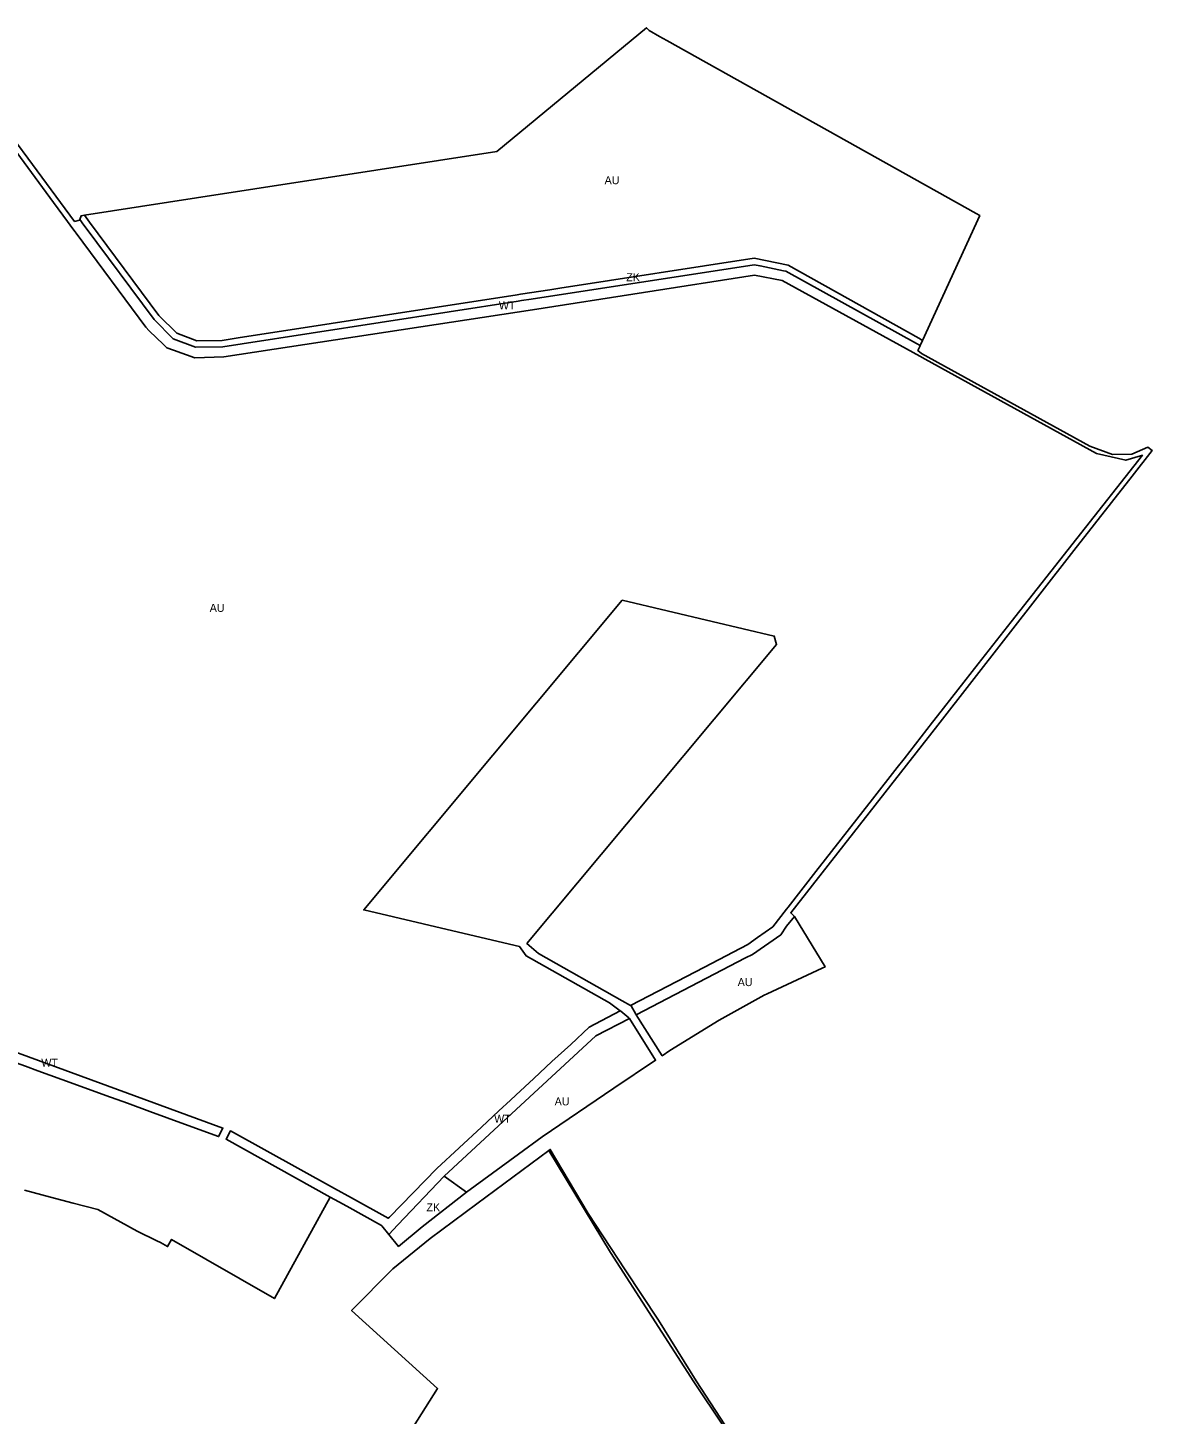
# Model space of a CAD drawing. Extents: x -541351 to -537540, y -1162694 to -1159725.
# Drawn here: x -538243 to -537540, y -1161316 to -1160450 of the extents above; entities that cross this region are included whole.
import ezdxf

# ---------------------------------------------------------------- set-up
doc = ezdxf.new("R2010")
doc.units = 0
for name, color, linetype in [('90640013', 7, 'Continuous'), ('90710013', 7, 'Continuous'), ('90750013', 7, 'Continuous')]:
    doc.layers.add(name, color=color, linetype=linetype)

msp = doc.modelspace()

# ---------------------------------------------------------------- linework, layer by layer
at = {"layer": '90640013'}
msp.add_lwpolyline([(-538279, -1160482.96), (-538213.92, -1160570.92), (-538210.85, -1160570.08), (-538210.69, -1160569.68), (-538208.11, -1160573.15), (-538207.25, -1160574.31), (-538164.14, -1160632.26), (-538152.14, -1160644.18), (-538138.21, -1160649.42), (-538121.28, -1160649.23), (-538109.03, -1160647.34), (-537936.47, -1160620.64), (-537934.5, -1160620.33), (-537928.39, -1160619.39), (-537789.11, -1160597.93), (-537785.28, -1160598.72), (-537770.7, -1160601.72), (-537769.21, -1160602.03), (-537687.55, -1160647.19), (-537685.23, -1160648.47), (-537685.51, -1160649.08), (-537686.66, -1160651.61), (-537684.47, -1160653.51), (-537579.13, -1160711.27), (-537565.07, -1160716.59), (-537552.97, -1160716.32), (-537542.86, -1160712.01), (-537540.13, -1160714.12), (-537552.67, -1160730.05), (-537589.07, -1160776.48), (-537674.22, -1160885.61), (-537766.11, -1161003.04), (-537763.7, -1161005.27), (-537768.77, -1161011.34), (-537772.4, -1161016.83), (-537790.07, -1161028.95), (-537794.44, -1161031.23), (-537862.75, -1161066.81), (-537863.04, -1161066.36), (-537865.95, -1161061.12), (-537866.26, -1161060.95), (-537820.17, -1161036.95), (-537802.13, -1161027.56), (-537793.05, -1161022.83), (-537786.92, -1161018.47), (-537777.42, -1161011.72), (-537768.74, -1161000.61), (-537767.82, -1160999.43), (-537750.43, -1160977.17), (-537715.05, -1160931.9), (-537699.56, -1160912.07), (-537695.33, -1160906.66), (-537677.47, -1160883.81), (-537674.39, -1160879.87), (-537648.96, -1160847.33), (-537628.36, -1160821.2), (-537546.25, -1160717.06), (-537547.58, -1160717.45), (-537556.76, -1160720.12), (-537575.01, -1160716.01), (-537682.14, -1160657.06), (-537685.53, -1160655.19), (-537771.5, -1160607.84), (-537788.88, -1160604.48), (-537927.57, -1160626.04), (-538120.6, -1160655.48), (-538138.75, -1160656.03), (-538151.96, -1160651.42), (-538156.16, -1160649.95), (-538158.3, -1160647.86), (-538167.16, -1160639.19), (-538169.34, -1160637.06), (-538212.88, -1160578.2), (-538213.5, -1160577.37), (-538214.91, -1160575.46), (-538218.22, -1160570.98), (-538227.05, -1160559.02), (-538238.54, -1160543.48), (-538272.58, -1160497.42)], dxfattribs=at)
for points in [[(-538375.11, -1161055.56), (-538368.36, -1161057.14), (-538292.2, -1161074.93), (-538121.13, -1161137.53), (-538123.8, -1161142.88), (-538145.25, -1161135.18), (-538166.87, -1161127.08), (-538180.71, -1161122.06), (-538194.34, -1161117.12), (-538209.76, -1161111.53), (-538221.89, -1161107.13), (-538236.85, -1161101.71), (-538244.47, -1161098.87), (-538261.65, -1161092.73), (-538269.37, -1161089.96), (-538288.24, -1161082.83), (-538291.28, -1161081.71), (-538292.78, -1161081.15), (-538313.99, -1161076.13), (-538334.92, -1161071.21), (-538344.15, -1161068.97), (-538360.05, -1161065.13), (-538370.98, -1161062.77)], [(-538017.371, -1161203.989), (-538021.73, -1161198.6), (-538021.99, -1161198.46), (-538043.663, -1161186.43), (-538048.69, -1161183.64), (-538054.155, -1161180.606), (-538054.155, -1161180.606), (-538119.15, -1161144.52), (-538116.49, -1161139.32), (-538051.28, -1161175.369), (-538040.778, -1161181.175), (-538017.76, -1161193.9), (-538017.1, -1161193.19), (-537987.47, -1161162.86), (-537959.49, -1161136.9), (-537948.57, -1161126.77), (-537941.41, -1161120.13), (-537938.08, -1161117.04), (-537926.78, -1161106.53), (-537915.45, -1161096.02), (-537903.69, -1161085.29), (-537892.24, -1161074.47), (-537872.72, -1161064.31), (-537872.42, -1161064.54), (-537867.27, -1161068.59), (-537867, -1161069.02), (-537887.98, -1161079.94), (-537948.84, -1161136.22), (-537982.73, -1161167.56), (-538011.8, -1161198.06)]]:
    msp.add_lwpolyline(points, close=True, dxfattribs=at)
at = {"layer": '90710013'}
for points in [[(-537770.7, -1160601.72), (-537785.28, -1160598.72), (-537789.11, -1160597.93), (-537928.39, -1160619.39), (-537934.5, -1160620.33), (-537936.47, -1160620.64), (-538109.03, -1160647.34), (-538121.28, -1160649.23), (-538138.21, -1160649.42), (-538152.14, -1160644.18), (-538164.14, -1160632.26), (-538207.25, -1160574.31), (-538208.11, -1160573.15), (-538210.69, -1160569.68), (-538209.76, -1160567.34), (-538207.69, -1160567.02), (-538204.55, -1160571.24), (-538161.11, -1160629.63), (-538149.93, -1160640.74), (-538137.51, -1160645.41), (-538121.61, -1160645.23), (-538111.7, -1160643.7), (-537937.08, -1160616.69), (-537935.11, -1160616.38), (-537916.68, -1160613.54), (-537910.61, -1160612.61), (-537789.01, -1160593.87), (-537767.82, -1160598.23), (-537686.06, -1160643.92), (-537683.74, -1160645.22), (-537685.23, -1160648.47), (-537687.55, -1160647.19), (-537769.21, -1160602.03)], [(-538017.371, -1161203.989), (-538011.8, -1161198.06), (-537982.73, -1161167.56), (-537968.86, -1161177.68), (-537996.47, -1161199.19), (-538011.287, -1161211.511)]]:
    msp.add_lwpolyline(points, close=True, dxfattribs=at)
msp.add_lwpolyline([(-537771.59, -1161378.63), (-537826.79, -1161296.05), (-537878.78, -1161215.29), (-537917.43, -1161151.64), (-537916.45, -1161150.91), (-537892.7, -1161190.89), (-537869.6, -1161226.04), (-537848.8, -1161257.55), (-537825.35, -1161295.54), (-537795.27, -1161341.6)], dxfattribs=at)
at = {"layer": '90750013'}
for points in [[(-537683.74, -1160645.22), (-537686.06, -1160643.92), (-537767.82, -1160598.23), (-537789.01, -1160593.87), (-537910.61, -1160612.61), (-537916.68, -1160613.54), (-537935.11, -1160616.38), (-537937.08, -1160616.69), (-538111.7, -1160643.7), (-538121.61, -1160645.23), (-538137.51, -1160645.41), (-538149.93, -1160640.74), (-538161.11, -1160629.63), (-538204.55, -1160571.24), (-538207.69, -1160567.02), (-538137.75, -1160556.21), (-537949.87, -1160527.25), (-537856.38, -1160449.82), (-537854.65, -1160451.57), (-537848.19, -1160455.22), (-537843.64, -1160457.79), (-537650.31, -1160565.94), (-537648.03, -1160567.22)], [(-537763.7, -1161005.27), (-537744.73, -1161036.78), (-537746.54, -1161037.51), (-537780.97, -1161053.72), (-537782.71, -1161054.54), (-537810.83, -1161070.12), (-537841.77, -1161089.11), (-537846.51, -1161092.3), (-537862.75, -1161066.81), (-537794.44, -1161031.23), (-537790.07, -1161028.95), (-537772.4, -1161016.83), (-537768.77, -1161011.34)], [(-537867, -1161069.02), (-537850.7, -1161095.11), (-537876.65, -1161112.57), (-537921.55, -1161143.01), (-537936.28, -1161153.8), (-537968.86, -1161177.68), (-537982.73, -1161167.56), (-537948.84, -1161136.22), (-537887.98, -1161079.94)]]:
    msp.add_lwpolyline(points, close=True, dxfattribs=at)
for points in [[(-538272.58, -1160497.42), (-538238.54, -1160543.48), (-538227.05, -1160559.02), (-538218.22, -1160570.98), (-538214.91, -1160575.46), (-538213.5, -1160577.37), (-538212.88, -1160578.2), (-538169.34, -1160637.06), (-538167.16, -1160639.19), (-538158.3, -1160647.86), (-538156.16, -1160649.95), (-538151.96, -1160651.42), (-538138.75, -1160656.03), (-538120.6, -1160655.48), (-537927.57, -1160626.04), (-537788.88, -1160604.48), (-537771.5, -1160607.84), (-537685.53, -1160655.19), (-537682.14, -1160657.06), (-537575.01, -1160716.01), (-537556.76, -1160720.12), (-537547.58, -1160717.45), (-537546.25, -1160717.06), (-537628.36, -1160821.2), (-537648.96, -1160847.33), (-537674.39, -1160879.87), (-537677.47, -1160883.81), (-537695.33, -1160906.66), (-537699.56, -1160912.07), (-537715.05, -1160931.9), (-537750.43, -1160977.17), (-537767.82, -1160999.43), (-537768.74, -1161000.61), (-537777.42, -1161011.72), (-537786.92, -1161018.47), (-537793.05, -1161022.83), (-537802.13, -1161027.56), (-537820.17, -1161036.95), (-537866.26, -1161060.95), (-537871.46, -1161058.02), (-537923.87, -1161028.46), (-537923.87, -1161028.46), (-537931.08, -1161022.13), (-537853.06, -1160928.71), (-537775.04, -1160835.28), (-537776.51, -1160829.99), (-537815.26, -1160820.89), (-537871.51, -1160807.67), (-537952.32, -1160904.42), (-538033.13, -1161001.17), (-537977.34, -1161014.29), (-537935.72, -1161024.07), (-537935.72, -1161024.07), (-537931.57, -1161029.91), (-537879.46, -1161059.19), (-537872.72, -1161064.31), (-537892.24, -1161074.47), (-537903.69, -1161085.29), (-537915.45, -1161096.02), (-537926.78, -1161106.53), (-537938.08, -1161117.04), (-537941.41, -1161120.13), (-537948.57, -1161126.77), (-537959.49, -1161136.9), (-537987.47, -1161162.86), (-538017.1, -1161193.19), (-538017.76, -1161193.9), (-538040.778, -1161181.175), (-538051.28, -1161175.369), (-538116.49, -1161139.32), (-538119.15, -1161144.52), (-538054.155, -1161180.606), (-538088.992, -1161244.066), (-538088.992, -1161244.066), (-538153.28, -1161207.14), (-538155.716, -1161211.579), (-538155.716, -1161211.579), (-538160.18, -1161209.13), (-538162.39, -1161208.04), (-538174.67, -1161201.96), (-538199.3, -1161188.32), (-538214.72, -1161184.39), (-538228.93, -1161180.63), (-538245.22, -1161176.32)], [(-538244.47, -1161098.87), (-538236.85, -1161101.71), (-538221.89, -1161107.13), (-538209.76, -1161111.53), (-538194.34, -1161117.12), (-538180.71, -1161122.06), (-538166.87, -1161127.08), (-538145.25, -1161135.18), (-538123.8, -1161142.88), (-538121.13, -1161137.53), (-538292.2, -1161074.93)], [(-538023.45, -1161358.02), (-537986.93, -1161300.34), (-538040.75, -1161251.55), (-538014.94, -1161225.48), (-537991.61, -1161206.61), (-537962.32, -1161184.95), (-537917.43, -1161151.64), (-537878.78, -1161215.29), (-537826.79, -1161296.05), (-537771.59, -1161378.63)]]:
    msp.add_lwpolyline(points, dxfattribs=at)

# ---------------------------------------------------------------- texts
at = {"layer": '90640013'}
for rotation, p in [(0, (-537948.62, -1160625.885)), (0, (-538234.676, -1161099.22)), (360, (-537951.563, -1161134.149))]:
    msp.add_text('WT', height=5, rotation=rotation, dxfattribs=at).set_placement(p)
at = {"layer": '90710013'}
for p in [(-537869.009, -1160608.22), (-537993.876, -1161189.535)]:
    msp.add_text('ZK', height=5, rotation=360, dxfattribs=at).set_placement(p)
at = {"layer": '90750013'}
for p in [(-537882.529, -1160547.615), (-538129.394, -1160814.903), (-537799.316, -1161048.785), (-537913.737, -1161123.35)]:
    msp.add_text('AU', height=5, rotation=0, dxfattribs=at).set_placement(p)

doc.saveas('drawing.dxf')
